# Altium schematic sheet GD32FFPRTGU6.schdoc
size 127 x 101 mm
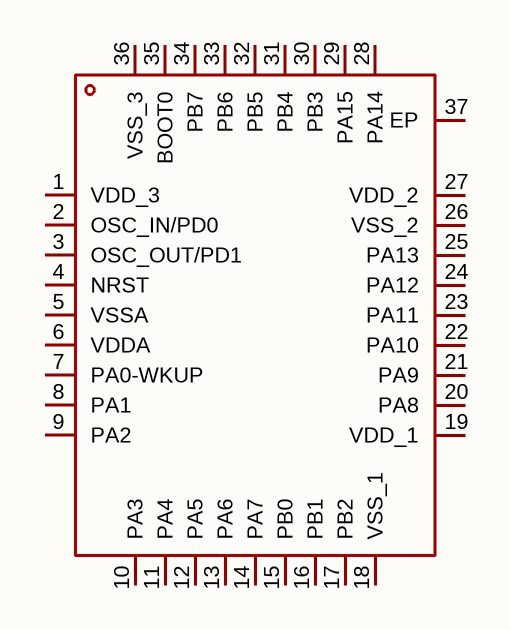
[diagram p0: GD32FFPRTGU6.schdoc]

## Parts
U?  gd32ffprtgu6  [QFN-36_L6.0-W6.0-P0.50-BL-EP]  (value not drawn)

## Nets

Not connected (* = marked no-connect by the designer): U? 1(VDD_3) 2(OSC_IN/PD0) 3(OSC_OUT/PD1) 4(NRST) 5(VSSA) 6(VDDA) 7(PA0-WKUP) 8(PA1) 9(PA2) 10(PA3) 11(PA4) 12(PA5) 13(PA6) 14(PA7) 15(PB0) 16(PB1) 17(PB2) 18(VSS_1) 19(VDD_1) 20(PA8) 21(PA9) 22(PA10) 23(PA11) 24(PA12) 25(PA13) 26(VSS_2) 27(VDD_2) 28(PA14) 29(PA15) 30(PB3) 31(PB4) 32(PB5) 33(PB6) 34(PB7) 35(BOOT0) 36(VSS_3) 37(EP)

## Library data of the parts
U? = gd32ffprtgu6: CPU内核:ARM Cortex-M4;CPU最大主频:168MHz;; Manufacturer: GigaDevice(兆易创新); AddInBom: yes; ModelId: 719dafc2dafb4a0c85b0e8fc2e781caa; ModelName: QFN-36_L6.0-W6.0-H1.0-P0.50; ModelTransform: 237.007,237.007,0,90,0,0,-0.0005,-0.0005,0; CPU Maximum Speed: 168MHz; Program Storage Size: 256KB; Program Memory Type: FLASH; Number of I/O: 26; ADC (Bit): 12bit; Voltage - Supply: 2.6V~3.6V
